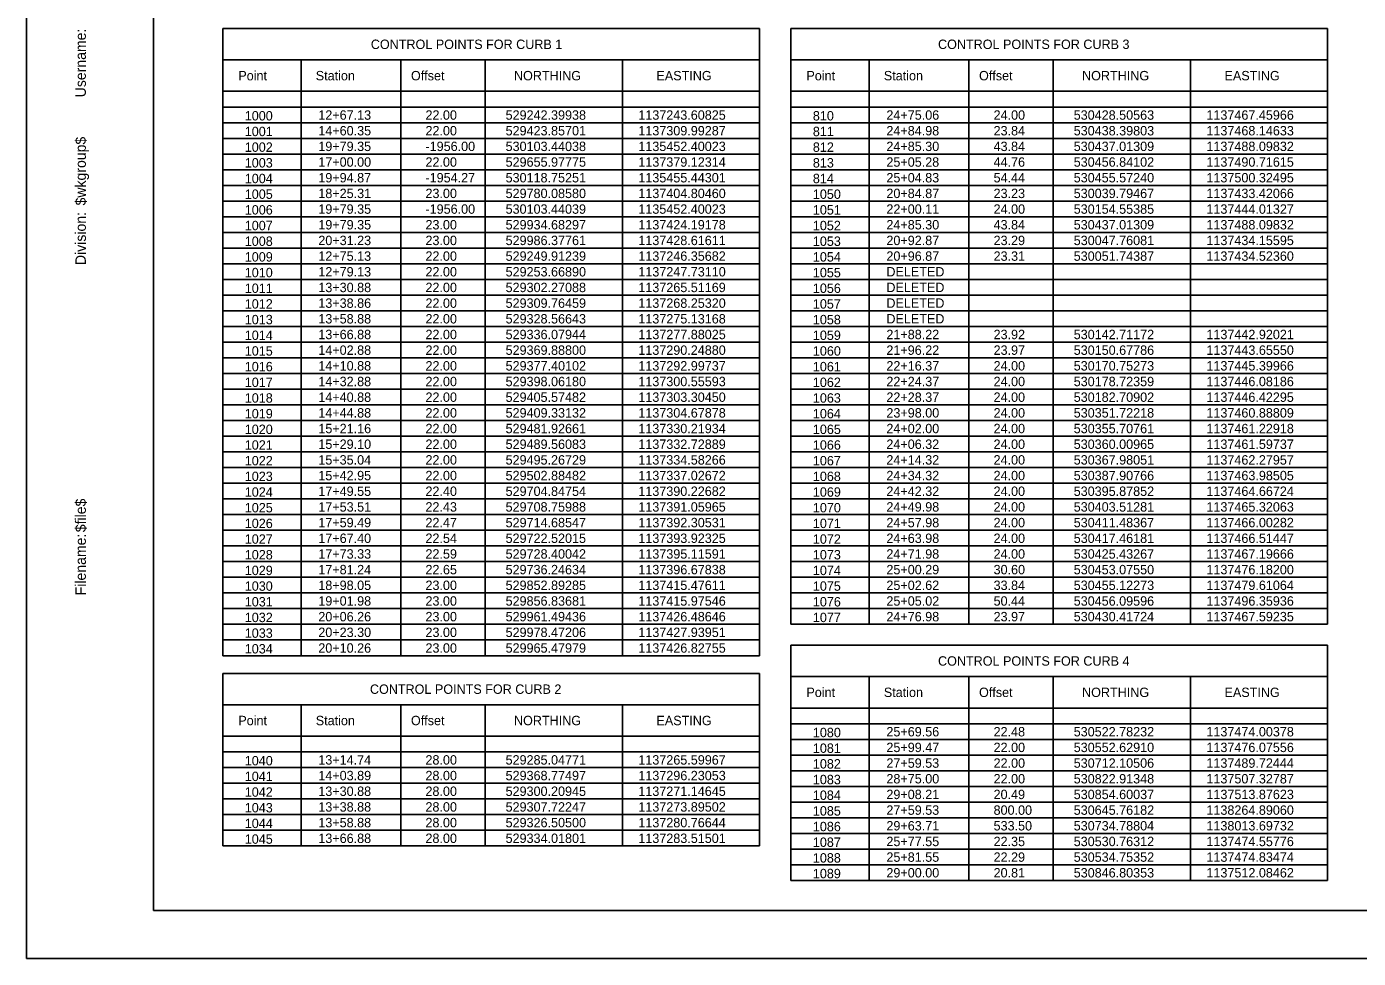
# Model space of a CAD drawing. Extents: x 0 to 850, y 0 to 550.
# Drawn here: x -0.1 to 424.7, y -0.1 to 297.1 of the extents above; entities that cross this region are included whole.
import ezdxf

# ---------------------------------------------------------------- set-up
doc = ezdxf.new("R2010")
doc.units = 0
for name, color, linetype in [('ANNOTATION', 7, 'Continuous'), ('BORDER', 7, 'Continuous'), ('Default', 7, 'Continuous'), ('H_V CONTROLS', 7, 'Continuous'), ('PLOT BOUNDARY', 7, 'Continuous')]:
    doc.layers.add(name, color=color, linetype=linetype)

msp = doc.modelspace()

# ---------------------------------------------------------------- linework, layer by layer
at = {"layer": 'BORDER'}
for p, q in [((40.33, 540.24), (40.33, 15.24)), ((40.33, 15.24), (840.33, 15.24))]:
    msp.add_line(p, q, dxfattribs=at)
at = {"layer": 'Default'}
msp.add_lwpolyline([(40.33, 15.24), (790.33, 15.24), (790.33, 540.26), (40.33, 540.26)], close=True, dxfattribs=at)
at = {"layer": 'H_V CONTROLS'}
for p, q in [((62.43, 296.49), (233.66, 296.49)), ((62.43, 296.49), (62.43, 96.49)), ((233.66, 296.49), (233.66, 96.49)), ((243.66, 296.49), (414.9, 296.49)), ((243.66, 296.49), (243.66, 106.49)), ((414.9, 296.49), (414.9, 106.49)), ((62.43, 286.49), (233.66, 286.49)), ((87.47, 286.49), (87.47, 96.49)), ((119.24, 286.49), (119.24, 96.49)), ((146.16, 286.49), (146.16, 96.49)), ((189.91, 286.49), (189.91, 96.49)), ((243.66, 286.49), (414.9, 286.49)), ((268.7, 286.49), (268.7, 106.49)), ((300.48, 286.49), (300.48, 106.49)), ((327.4, 286.49), (327.4, 106.49)), ((371.15, 286.49), (371.15, 106.49)), ((62.43, 276.49), (233.66, 276.49)), ((243.66, 276.49), (414.9, 276.49)), ((62.43, 271.49), (233.66, 271.49)), ((243.66, 271.49), (414.9, 271.49)), ((62.43, 266.49), (233.66, 266.49)), ((243.66, 266.49), (414.9, 266.49)), ((62.43, 261.49), (233.66, 261.49)), ((243.66, 261.49), (414.9, 261.49)), ((62.43, 256.49), (233.66, 256.49)), ((243.66, 256.49), (414.9, 256.49)), ((62.43, 251.49), (233.66, 251.49)), ((243.66, 251.49), (414.9, 251.49)), ((62.43, 246.49), (233.66, 246.49)), ((243.66, 246.49), (414.9, 246.49)), ((62.43, 241.49), (233.66, 241.49)), ((243.66, 241.49), (414.9, 241.49)), ((62.43, 236.49), (233.66, 236.49)), ((243.66, 236.49), (414.9, 236.49)), ((62.43, 231.49), (233.66, 231.49)), ((243.66, 231.49), (414.9, 231.49)), ((62.43, 226.49), (233.66, 226.49)), ((243.66, 226.49), (414.9, 226.49)), ((62.43, 221.49), (233.66, 221.49)), ((243.66, 221.49), (414.9, 221.49)), ((62.43, 216.49), (233.66, 216.49)), ((243.66, 216.49), (414.9, 216.49)), ((62.43, 211.49), (233.66, 211.49)), ((243.66, 211.49), (414.9, 211.49)), ((62.43, 206.49), (233.66, 206.49)), ((243.66, 206.49), (414.9, 206.49)), ((62.43, 201.49), (233.66, 201.49)), ((243.66, 201.49), (414.9, 201.49)), ((62.43, 196.49), (233.66, 196.49)), ((243.66, 196.49), (414.9, 196.49)), ((62.43, 191.49), (233.66, 191.49)), ((243.66, 191.49), (414.9, 191.49)), ((62.43, 186.49), (233.66, 186.49)), ((243.66, 186.49), (414.9, 186.49)), ((62.43, 181.49), (233.66, 181.49)), ((243.66, 181.49), (414.9, 181.49)), ((62.43, 176.49), (233.66, 176.49)), ((243.66, 176.49), (414.9, 176.49)), ((62.43, 171.49), (233.66, 171.49)), ((243.66, 171.49), (414.9, 171.49)), ((62.43, 166.49), (233.66, 166.49)), ((243.66, 166.49), (414.9, 166.49)), ((62.43, 161.49), (233.66, 161.49)), ((243.66, 161.49), (414.9, 161.49)), ((62.43, 156.49), (233.66, 156.49)), ((243.66, 156.49), (414.9, 156.49)), ((62.43, 151.49), (233.66, 151.49)), ((243.66, 151.49), (414.9, 151.49)), ((62.43, 146.49), (233.66, 146.49)), ((243.66, 146.49), (414.9, 146.49)), ((62.43, 141.49), (233.66, 141.49)), ((243.66, 141.49), (414.9, 141.49)), ((62.43, 136.49), (233.66, 136.49)), ((243.66, 136.49), (414.9, 136.49)), ((62.43, 131.49), (233.66, 131.49)), ((243.66, 131.49), (414.9, 131.49)), ((62.43, 126.49), (233.66, 126.49)), ((243.66, 126.49), (414.9, 126.49)), ((62.43, 121.49), (233.66, 121.49)), ((243.66, 121.49), (414.9, 121.49)), ((62.43, 116.49), (233.66, 116.49)), ((243.66, 116.49), (414.9, 116.49)), ((62.43, 111.49), (233.66, 111.49)), ((243.66, 111.49), (414.9, 111.49)), ((62.43, 106.49), (233.66, 106.49)), ((243.66, 106.49), (414.9, 106.49)), ((62.43, 101.49), (233.66, 101.49)), ((243.66, 99.8), (414.9, 99.8)), ((243.66, 99.8), (243.66, 24.8)), ((414.9, 99.8), (414.9, 24.8)), ((62.43, 96.49), (233.66, 96.49)), ((62.43, 90.81), (233.66, 90.81)), ((62.43, 90.81), (62.43, 35.81)), ((233.66, 90.81), (233.66, 35.81)), ((243.66, 89.8), (414.9, 89.8)), ((268.7, 89.8), (268.7, 24.8)), ((300.48, 89.8), (300.48, 24.8)), ((327.4, 89.8), (327.4, 24.8)), ((371.15, 89.8), (371.15, 24.8)), ((62.43, 80.81), (233.66, 80.81)), ((87.47, 80.81), (87.47, 35.81)), ((119.24, 80.81), (119.24, 35.81)), ((146.16, 80.81), (146.16, 35.81)), ((189.91, 80.81), (189.91, 35.81)), ((243.66, 79.8), (414.9, 79.8)), ((243.66, 74.8), (414.9, 74.8)), ((62.43, 70.81), (233.66, 70.81)), ((243.66, 69.8), (414.9, 69.8)), ((62.43, 65.81), (233.66, 65.81)), ((243.66, 64.8), (414.9, 64.8)), ((62.43, 60.81), (233.66, 60.81)), ((243.66, 59.8), (414.9, 59.8)), ((62.43, 55.81), (233.66, 55.81)), ((243.66, 54.8), (414.9, 54.8)), ((62.43, 50.81), (233.66, 50.81)), ((243.66, 49.8), (414.9, 49.8)), ((62.43, 45.81), (233.66, 45.81)), ((243.66, 44.8), (414.9, 44.8)), ((62.43, 40.81), (233.66, 40.81)), ((243.66, 39.8), (414.9, 39.8)), ((62.43, 35.81), (233.66, 35.81)), ((243.66, 34.8), (414.9, 34.8)), ((243.66, 29.8), (414.9, 29.8)), ((243.66, 24.8), (414.9, 24.8))]:
    msp.add_line(p, q, dxfattribs=at)
at = {"layer": 'PLOT BOUNDARY'}
msp.add_lwpolyline([(-0.13, -0.05), (849.87, -0.05), (849.87, 549.95), (-0.13, 549.95)], close=True, dxfattribs=at)

# ---------------------------------------------------------------- texts
at = {"layer": 'ANNOTATION'}
for s, p in [('1000', (69.46, 267.19)), ('12+67.13', (92.92, 267.43)), ('22.00', (127.1, 267.43)), ('529242.39938', (152.66, 267.43)), ('1137243.60825', (195.01, 267.43)), ('810', (250.69, 267.19)), ('24+75.06', (274.15, 267.43)), ('24.00', (308.34, 267.43)), ('530428.50563', (333.9, 267.43)), ('1137467.45966', (376.24, 267.43)), ('1001', (69.46, 262.19)), ('14+60.35', (92.92, 262.43)), ('22.00', (127.1, 262.43)), ('529423.85701', (152.66, 262.43)), ('1137309.99287', (195.01, 262.43)), ('811', (250.69, 262.19)), ('24+84.98', (274.15, 262.43)), ('23.84', (308.34, 262.43)), ('530438.39803', (333.9, 262.43)), ('1137468.14633', (376.24, 262.43)), ('1002', (69.46, 257.19)), ('19+79.35', (92.92, 257.44)), ('-1956.00', (127.1, 257.44)), ('530103.44038', (152.66, 257.44)), ('1135452.40023', (195.01, 257.44)), ('812', (250.69, 257.19)), ('24+85.30', (274.15, 257.44)), ('43.84', (308.34, 257.44)), ('530437.01309', (333.9, 257.44)), ('1137488.09832', (376.24, 257.44)), ('1003', (69.46, 252.19)), ('17+00.00', (92.92, 252.44)), ('22.00', (127.1, 252.44)), ('529655.97775', (152.66, 252.44)), ('1137379.12314', (195.01, 252.44)), ('813', (250.69, 252.19)), ('25+05.28', (274.15, 252.44)), ('44.76', (308.34, 252.44)), ('530456.84102', (333.9, 252.44)), ('1137490.71615', (376.24, 252.44)), ('1004', (69.46, 247.19)), ('19+94.87', (92.92, 247.44)), ('-1954.27', (127.1, 247.44)), ('530118.75251', (152.66, 247.44)), ('1135455.44301', (195.01, 247.44)), ('814', (250.69, 247.19)), ('25+04.83', (274.15, 247.44)), ('54.44', (308.34, 247.44)), ('530455.57240', (333.9, 247.44)), ('1137500.32495', (376.24, 247.44)), ('1005', (69.46, 242.19)), ('18+25.31', (92.92, 242.44)), ('23.00', (127.1, 242.44)), ('529780.08580', (152.66, 242.44)), ('1137404.80460', (195.01, 242.44)), ('1050', (250.69, 242.19)), ('20+84.87', (274.15, 242.44)), ('23.23', (308.34, 242.44)), ('530039.79467', (333.9, 242.44)), ('1137433.42066', (376.24, 242.44)), ('1006', (69.46, 237.19)), ('19+79.35', (92.92, 237.44)), ('-1956.00', (127.1, 237.44)), ('530103.44039', (152.66, 237.44)), ('1135452.40023', (195.01, 237.44)), ('1051', (250.69, 237.19)), ('22+00.11', (274.15, 237.44)), ('24.00', (308.34, 237.44)), ('530154.55385', (333.9, 237.44)), ('1137444.01327', (376.24, 237.44)), ('1007', (69.46, 232.19)), ('19+79.35', (92.92, 232.44)), ('23.00', (127.1, 232.44)), ('529934.68297', (152.66, 232.44)), ('1137424.19178', (195.01, 232.44)), ('1052', (250.69, 232.19)), ('24+85.30', (274.15, 232.44)), ('43.84', (308.34, 232.44)), ('530437.01309', (333.9, 232.44)), ('1137488.09832', (376.24, 232.44)), ('1008', (69.46, 227.19)), ('20+31.23', (92.92, 227.44)), ('23.00', (127.1, 227.44)), ('529986.37761', (152.66, 227.44)), ('1137428.61611', (195.01, 227.44)), ('1053', (250.69, 227.19)), ('20+92.87', (274.15, 227.44)), ('23.29', (308.34, 227.44)), ('530047.76081', (333.9, 227.44)), ('1137434.15595', (376.24, 227.44)), ('1009', (69.46, 222.19)), ('12+75.13', (92.92, 222.44)), ('22.00', (127.1, 222.44)), ('529249.91239', (152.66, 222.44)), ('1137246.35682', (195.01, 222.44)), ('1054', (250.69, 222.19)), ('20+96.87', (274.15, 222.44)), ('23.31', (308.34, 222.44)), ('530051.74387', (333.9, 222.44)), ('1137434.52360', (376.24, 222.44)), ('1010', (69.46, 217.19)), ('12+79.13', (92.92, 217.44)), ('22.00', (127.1, 217.44)), ('529253.66890', (152.66, 217.44)), ('1137247.73110', (195.01, 217.44)), ('1055', (250.69, 217.19)), ('DELETED', (274.15, 217.44)), ('1011', (69.46, 212.19)), ('13+30.88', (92.92, 212.44)), ('22.00', (127.1, 212.44)), ('529302.27088', (152.66, 212.44)), ('1137265.51169', (195.01, 212.44)), ('1056', (250.69, 212.19)), ('DELETED', (274.15, 212.44)), ('1012', (69.46, 207.19)), ('13+38.86', (92.92, 207.44)), ('22.00', (127.1, 207.44)), ('529309.76459', (152.66, 207.44)), ('1137268.25320', (195.01, 207.44)), ('1057', (250.69, 207.19)), ('DELETED', (274.15, 207.44)), ('1013', (69.46, 202.19)), ('13+58.88', (92.92, 202.44)), ('22.00', (127.1, 202.44)), ('529328.56643', (152.66, 202.44)), ('1137275.13168', (195.01, 202.44)), ('1058', (250.69, 202.19)), ('DELETED', (274.15, 202.44)), ('1014', (69.46, 197.19)), ('13+66.88', (92.92, 197.44)), ('22.00', (127.1, 197.44)), ('529336.07944', (152.66, 197.44)), ('1137277.88025', (195.01, 197.44)), ('1059', (250.69, 197.19)), ('21+88.22', (274.15, 197.44)), ('23.92', (308.34, 197.44)), ('530142.71172', (333.9, 197.44)), ('1137442.92021', (376.24, 197.44)), ('14+02.88', (92.92, 192.44)), ('22.00', (127.1, 192.44)), ('529369.88800', (152.66, 192.44)), ('1137290.24880', (195.01, 192.44)), ('21+96.22', (274.15, 192.44)), ('23.97', (308.34, 192.44)), ('530150.67786', (333.9, 192.44)), ('1137443.65550', (376.24, 192.44)), ('1015', (69.46, 192.19)), ('1060', (250.69, 192.19)), ('1016', (69.46, 187.19)), ('14+10.88', (92.92, 187.44)), ('22.00', (127.1, 187.44)), ('529377.40102', (152.66, 187.44)), ('1137292.99737', (195.01, 187.44)), ('1061', (250.69, 187.19)), ('22+16.37', (274.15, 187.44)), ('24.00', (308.34, 187.44)), ('530170.75273', (333.9, 187.44)), ('1137445.39966', (376.24, 187.44)), ('1017', (69.46, 182.19)), ('14+32.88', (92.92, 182.44)), ('22.00', (127.1, 182.44)), ('529398.06180', (152.66, 182.44)), ('1137300.55593', (195.01, 182.44)), ('1062', (250.69, 182.19)), ('22+24.37', (274.15, 182.44)), ('24.00', (308.34, 182.44)), ('530178.72359', (333.9, 182.44)), ('1137446.08186', (376.24, 182.44)), ('1018', (69.46, 177.19)), ('14+40.88', (92.92, 177.44)), ('22.00', (127.1, 177.44)), ('529405.57482', (152.66, 177.44)), ('1137303.30450', (195.01, 177.44)), ('1063', (250.69, 177.19)), ('22+28.37', (274.15, 177.44)), ('24.00', (308.34, 177.44)), ('530182.70902', (333.9, 177.44)), ('1137446.42295', (376.24, 177.44)), ('1019', (69.46, 172.19)), ('14+44.88', (92.92, 172.44)), ('22.00', (127.1, 172.44)), ('529409.33132', (152.66, 172.44)), ('1137304.67878', (195.01, 172.44)), ('1064', (250.69, 172.19)), ('23+98.00', (274.15, 172.44)), ('24.00', (308.34, 172.44)), ('530351.72218', (333.9, 172.44)), ('1137460.88809', (376.24, 172.44)), ('1020', (69.46, 167.19)), ('15+21.16', (92.92, 167.44)), ('22.00', (127.1, 167.44)), ('529481.92661', (152.66, 167.44)), ('1137330.21934', (195.01, 167.44)), ('1065', (250.69, 167.19)), ('24+02.00', (274.15, 167.44)), ('24.00', (308.34, 167.44)), ('530355.70761', (333.9, 167.44)), ('1137461.22918', (376.24, 167.44)), ('1021', (69.46, 162.19)), ('15+29.10', (92.92, 162.44)), ('22.00', (127.1, 162.44)), ('529489.56083', (152.66, 162.44)), ('1137332.72889', (195.01, 162.44)), ('1066', (250.69, 162.19)), ('24+06.32', (274.15, 162.44)), ('24.00', (308.34, 162.44)), ('530360.00965', (333.9, 162.44)), ('1137461.59737', (376.24, 162.44)), ('1022', (69.46, 157.19)), ('15+35.04', (92.92, 157.44)), ('22.00', (127.1, 157.44)), ('529495.26729', (152.66, 157.44)), ('1137334.58266', (195.01, 157.44)), ('1067', (250.69, 157.19)), ('24+14.32', (274.15, 157.44)), ('24.00', (308.34, 157.44)), ('530367.98051', (333.9, 157.44)), ('1137462.27957', (376.24, 157.44)), ('1023', (69.46, 152.19)), ('15+42.95', (92.92, 152.44)), ('22.00', (127.1, 152.44)), ('529502.88482', (152.66, 152.44)), ('1137337.02672', (195.01, 152.44)), ('1068', (250.69, 152.19)), ('24+34.32', (274.15, 152.44)), ('24.00', (308.34, 152.44)), ('530387.90766', (333.9, 152.44)), ('1137463.98505', (376.24, 152.44)), ('1024', (69.46, 147.19)), ('17+49.55', (92.92, 147.44)), ('22.40', (127.1, 147.44)), ('529704.84754', (152.66, 147.44)), ('1137390.22682', (195.01, 147.44)), ('1069', (250.69, 147.19)), ('24+42.32', (274.15, 147.44)), ('24.00', (308.34, 147.44)), ('530395.87852', (333.9, 147.44)), ('1137464.66724', (376.24, 147.44)), ('1025', (69.46, 142.19)), ('17+53.51', (92.92, 142.44)), ('22.43', (127.1, 142.44)), ('529708.75988', (152.66, 142.44)), ('1137391.05965', (195.01, 142.44)), ('1070', (250.69, 142.19)), ('24+49.98', (274.15, 142.44)), ('24.00', (308.34, 142.44)), ('530403.51281', (333.9, 142.44)), ('1137465.32063', (376.24, 142.44)), ('1026', (69.46, 137.19)), ('17+59.49', (92.92, 137.44)), ('22.47', (127.1, 137.44)), ('529714.68547', (152.66, 137.44)), ('1137392.30531', (195.01, 137.44)), ('1071', (250.69, 137.19)), ('24+57.98', (274.15, 137.44)), ('24.00', (308.34, 137.44)), ('530411.48367', (333.9, 137.44)), ('1137466.00282', (376.24, 137.44)), ('1027', (69.46, 132.19)), ('17+67.40', (92.92, 132.44)), ('22.54', (127.1, 132.44)), ('529722.52015', (152.66, 132.44)), ('1137393.92325', (195.01, 132.44)), ('1072', (250.69, 132.19)), ('24+63.98', (274.15, 132.44)), ('24.00', (308.34, 132.44)), ('530417.46181', (333.9, 132.44)), ('1137466.51447', (376.24, 132.44)), ('1028', (69.46, 127.19)), ('17+73.33', (92.92, 127.44)), ('22.59', (127.1, 127.44)), ('529728.40042', (152.66, 127.44)), ('1137395.11591', (195.01, 127.44)), ('1073', (250.69, 127.19)), ('24+71.98', (274.15, 127.44)), ('24.00', (308.34, 127.44)), ('530425.43267', (333.9, 127.44)), ('1137467.19666', (376.24, 127.44)), ('1029', (69.46, 122.19)), ('17+81.24', (92.92, 122.44)), ('22.65', (127.1, 122.44)), ('529736.24634', (152.66, 122.44)), ('1137396.67838', (195.01, 122.44)), ('1074', (250.69, 122.19)), ('25+00.29', (274.15, 122.44)), ('30.60', (308.34, 122.44)), ('530453.07550', (333.9, 122.44)), ('1137476.18200', (376.24, 122.44)), ('1030', (69.46, 117.19)), ('18+98.05', (92.92, 117.44)), ('23.00', (127.1, 117.44)), ('529852.89285', (152.66, 117.44)), ('1137415.47611', (195.01, 117.44)), ('1075', (250.69, 117.19)), ('25+02.62', (274.15, 117.44)), ('33.84', (308.34, 117.44)), ('530455.12273', (333.9, 117.44)), ('1137479.61064', (376.24, 117.44)), ('1031', (69.46, 112.19)), ('19+01.98', (92.92, 112.44)), ('23.00', (127.1, 112.44)), ('529856.83681', (152.66, 112.44)), ('1137415.97546', (195.01, 112.44)), ('1076', (250.69, 112.19)), ('25+05.02', (274.15, 112.44)), ('50.44', (308.34, 112.44)), ('530456.09596', (333.9, 112.44)), ('1137496.35936', (376.24, 112.44)), ('20+06.26', (92.92, 107.44)), ('23.00', (127.1, 107.44)), ('529961.49436', (152.66, 107.44)), ('1137426.48646', (195.01, 107.44)), ('24+76.98', (274.15, 107.44)), ('23.97', (308.34, 107.44)), ('530430.41724', (333.9, 107.44)), ('1137467.59235', (376.24, 107.44)), ('1032', (69.46, 107.19)), ('1077', (250.69, 107.19)), ('1033', (69.46, 102.19)), ('20+23.30', (92.92, 102.44)), ('23.00', (127.1, 102.44)), ('529978.47206', (152.66, 102.44)), ('1137427.93951', (195.01, 102.44)), ('1034', (69.46, 97.19)), ('20+10.26', (92.92, 97.44)), ('23.00', (127.1, 97.44)), ('529965.47979', (152.66, 97.44)), ('1137426.82755', (195.01, 97.44)), ('1080', (250.69, 70.49)), ('25+69.56', (274.15, 70.74)), ('22.48', (308.34, 70.74)), ('530522.78232', (333.9, 70.74)), ('1137474.00378', (376.24, 70.74)), ('1081', (250.69, 65.49)), ('25+99.47', (274.15, 65.74)), ('22.00', (308.34, 65.74)), ('530552.62910', (333.9, 65.74)), ('1137476.07556', (376.24, 65.74)), ('1040', (69.46, 61.5)), ('13+14.74', (92.92, 61.75)), ('28.00', (127.1, 61.75)), ('529285.04771', (152.66, 61.75)), ('1137265.59967', (195.01, 61.75)), ('27+59.53', (274.15, 60.74)), ('22.00', (308.34, 60.74)), ('530712.10506', (333.9, 60.74)), ('1137489.72444', (376.24, 60.74)), ('1041', (69.46, 56.5)), ('14+03.89', (92.92, 56.75)), ('28.00', (127.1, 56.75)), ('529368.77497', (152.66, 56.75)), ('1137296.23053', (195.01, 56.75)), ('1082', (250.69, 60.49)), ('1083', (250.69, 55.49)), ('28+75.00', (274.15, 55.74)), ('22.00', (308.34, 55.74)), ('530822.91348', (333.9, 55.74)), ('1137507.32787', (376.24, 55.74)), ('1042', (69.46, 51.5)), ('13+30.88', (92.92, 51.75)), ('28.00', (127.1, 51.75)), ('529300.20945', (152.66, 51.75)), ('1137271.14645', (195.01, 51.75)), ('1084', (250.69, 50.49)), ('29+08.21', (274.15, 50.74)), ('20.49', (308.34, 50.74)), ('530854.60037', (333.9, 50.74)), ('1137513.87623', (376.24, 50.74)), ('1043', (69.46, 46.5)), ('13+38.88', (92.92, 46.75)), ('28.00', (127.1, 46.75)), ('529307.72247', (152.66, 46.75)), ('1137273.89502', (195.01, 46.75)), ('1085', (250.69, 45.49)), ('27+59.53', (274.15, 45.74)), ('800.00', (308.34, 45.74)), ('530645.76182', (333.9, 45.74)), ('1138264.89060', (376.24, 45.74)), ('1044', (69.46, 41.5)), ('13+58.88', (92.92, 41.75)), ('28.00', (127.1, 41.75)), ('529326.50500', (152.66, 41.75)), ('1137280.76644', (195.01, 41.75)), ('1086', (250.69, 40.5)), ('29+63.71', (274.15, 40.74)), ('533.50', (308.34, 40.74)), ('530734.78804', (333.9, 40.74)), ('1138013.69732', (376.24, 40.74)), ('1045', (69.46, 36.5)), ('13+66.88', (92.92, 36.75)), ('28.00', (127.1, 36.75)), ('529334.01801', (152.66, 36.75)), ('1137283.51501', (195.01, 36.75)), ('1087', (250.69, 35.5)), ('25+77.55', (274.15, 35.74)), ('22.35', (308.34, 35.74)), ('530530.76312', (333.9, 35.74)), ('1137474.55776', (376.24, 35.74)), ('1088', (250.69, 30.5)), ('25+81.55', (274.15, 30.75)), ('22.29', (308.34, 30.75)), ('530534.75352', (333.9, 30.75)), ('1137474.83474', (376.24, 30.75)), ('1089', (250.69, 25.5)), ('29+00.00', (274.15, 25.75)), ('20.81', (308.34, 25.75)), ('530846.80353', (333.9, 25.75)), ('1137512.08462', (376.24, 25.75))]:
    msp.add_text(s, height=3, rotation=360, dxfattribs=at).set_placement(p)
at = {"layer": 'BORDER'}
for s, p in [('Username:', (18.76, 274.58)), ('$wkgroup$', (18.76, 240.09)), ('Division:', (18.76, 221.08)), ('$file$', (18.76, 135.87)), ('Filename:', (18.76, 115.74))]:
    msp.add_text(s, height=3.348, rotation=90, dxfattribs=at).set_placement(p)
at = {"layer": 'H_V CONTROLS'}
for s, p in [('CONTROL POINTS FOR CURB 1', (109.67, 289.99)), ('CONTROL POINTS FOR CURB 3', (290.62, 289.99)), ('Point', (67.4, 279.99)), ('Station', (92.1, 279.99)), ('Offset', (122.47, 279.99)), ('NORTHING', (155.34, 279.99)), ('EASTING', (200.79, 279.99)), ('Point', (248.63, 279.99)), ('Station', (273.33, 279.99)), ('Offset', (303.7, 279.99)), ('NORTHING', (336.57, 279.99)), ('EASTING', (382.02, 279.99)), ('CONTROL POINTS FOR CURB 4', (290.62, 93.3)), ('CONTROL POINTS FOR CURB 2', (109.39, 84.31)), ('Point', (248.63, 83.3)), ('Station', (273.33, 83.3)), ('Offset', (303.7, 83.3)), ('NORTHING', (336.57, 83.3)), ('EASTING', (382.02, 83.3)), ('Point', (67.4, 74.31)), ('Station', (92.1, 74.31)), ('Offset', (122.47, 74.31)), ('NORTHING', (155.34, 74.31)), ('EASTING', (200.79, 74.31))]:
    msp.add_text(s, height=3, rotation=360, dxfattribs=at).set_placement(p)

doc.saveas('drawing.dxf')
